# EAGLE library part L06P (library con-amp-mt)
AMP MT CONNECTOR
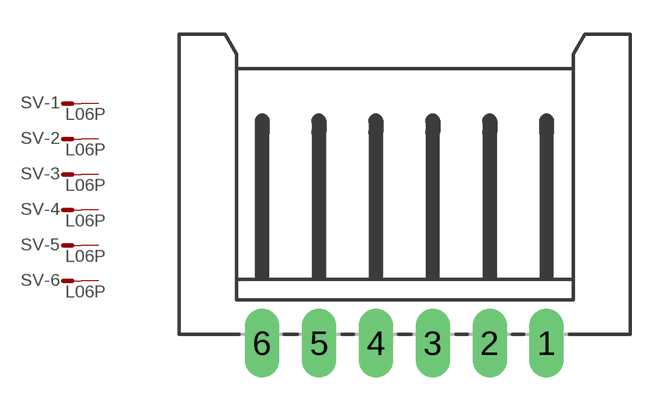
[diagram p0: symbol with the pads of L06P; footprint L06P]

Designator prefix SV; gates -1=M -2=M -3=M -4=M -5=M -6=M

## L06P (OC_FARNELL: unknown; OC_NEWARK: unknown)  [L06P]
1  -1:S  pas
2  -2:S  pas
3  -3:S  pas
4  -4:S  pas
5  -5:S  pas
6  -6:S  pas

## Footprint L06P (pad centres in mm)
AMP MT CONNECTOR
drill 1.016 long: 1 6.25,-6.25; 2 3.75,-6.25; 3 1.25,-6.25; 4 -1.25,-6.25; 5 -3.75,-6.25; 6 -6.25,-6.25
